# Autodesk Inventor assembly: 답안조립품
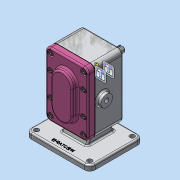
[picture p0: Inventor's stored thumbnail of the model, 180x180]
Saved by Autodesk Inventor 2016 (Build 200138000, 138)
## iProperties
Created: 2020-04
Part Number: 답안조립품
Document SubType Name: Assembly
Designer: MIRAE
Author: MIRAE
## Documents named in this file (11)
- C:\Users\MIRAE\Desktop\700407V1028\답안조립품.iam
- C:\Users\MIRAE\Desktop\700407V1028\본체.ipt
- C:\Users\MIRAE\Desktop\700407V1028\베어링부시.ipt
- C:\Users\MIRAE\Desktop\700407V1028\메인축.ipt
- C:\Users\MIRAE\Desktop\700407V1028\서브축.ipt
- C:\Users\MIRAE\Desktop\700407V1028\키 6 x 6 x 18.ipt
- C:\Users\MIRAE\Desktop\700407V1028\스퍼기어.ipt
- C:\Users\MIRAE\Desktop\700407V1028\개스킷.ipt
- C:\Users\MIRAE\Desktop\700407V1028\커버.ipt
- C:\Users\MIRAE\Desktop\700407V1028\볼트 M5.ipt
- C:\Users\MIRAE\Desktop\700407V1028\오일 실 16 28 7.ipt
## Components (1 placed, 1 different names)
1. 개스킷:1
